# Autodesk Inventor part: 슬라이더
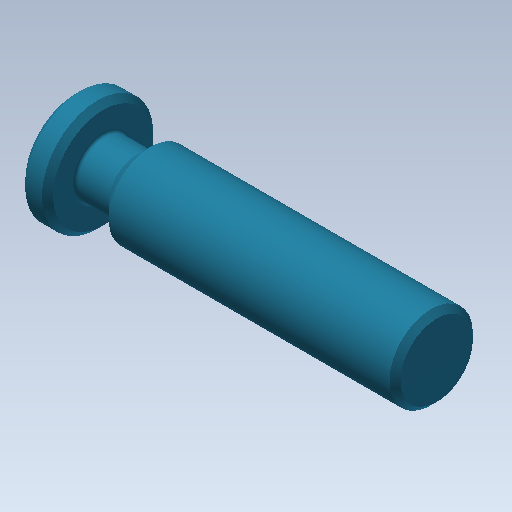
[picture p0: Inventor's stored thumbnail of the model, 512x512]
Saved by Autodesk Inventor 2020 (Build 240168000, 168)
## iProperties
Created: 2016-05
Part Number: 슬라이더
Document SubType Name: Modeling
Designer: mduedu
Density: 7.86 g/cm^3
Material: 강철, 연강
Appearance: 터키옥색
Author: mduedu
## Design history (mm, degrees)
sketch "스케치1"
  geometry: L1 (-7.5, 0)-(57.5, 0); L2 (57.5, 0)-(57.5, 7.5); L3 (57.5, 7.5)-(0, 7.5); L4 (-7.5, 0)-(-7.5, 10); L5 (-7.5, 10)-(-2.5, 10); L6 (-2.5, 10)-(-2.5, 5); L7 (-2.5, 5)-(3.5, 5); L8 (3.5, 5)-(6, 7.5); A1 r 7.5 centre (0, 0) between (0, 7.5) and (-7.5, 0); 1 further point
  constraints: 16 end point, 3 perpendicular, 2 horizontal, 2 parallel, 2 point on circle, 2 point on line, 2 tangent, 1 centre point, 1 coincident
  dimensions: "d0" = 15 diameter of A1; "d1" = 65 distance of L1.start L1.end; "d19" = 20 diameter of L5 L1; "d20" = 10 diameter of L7 L1; "d21" = 5 distance of L4.end L5.end; "d22" = 135 deg angle of L8 L7; "d23" = 6 distance of L6.end L7.end
revolve "회전1" stored, may be unused: angle "d4" = 90 deg
chamfer "모따기2" distance "d24" = 1; stored, may be unused: second distance "d25" = 2, angle "d26" = 45 deg
fillet "모깎기1" dims "d27" = 0.5
node "솔리드1"
